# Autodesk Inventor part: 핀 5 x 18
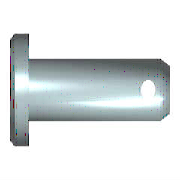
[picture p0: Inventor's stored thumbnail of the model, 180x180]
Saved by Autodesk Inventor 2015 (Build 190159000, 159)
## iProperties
Created: 2012-02
Part Number: 핀 5 x 18
Material: 강철
Description: 머리가 있는 클레비스 핀
Document SubType Name: Modeling
Standard: ISO 2341
Designer: test
Standard Revision: Second edition 1986-11-01
Standards Organization: ISO
Language: ko-KR
Size Designation: B - 5 x 18
Categories: <MemberInstance><Categories><Category DisplayName="조임쇠" InternalName="e4da775c-781d-43d5-af7c-5136215cf5a6" Mnemonic="FSTN"><Category DisplayName="핀" InternalNa
Density: 7.85 g/cm^3
Appearance: 강철
IsCustomPart: 1
Author: test
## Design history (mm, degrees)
sketch "스케치1"
  geometry: L1 (-1.6, 0)-(-1.6, 4); L2 (-1.6, 4)-(0, 4); L3 (0, 4)-(0, 2.5); L4 (0, 2.5)-(18, 2.5); L5 (18, 2.5)-(18, 0); L6 (-1.6, 0)-(18, 0); L7 (-4, 0)-(17, 0) reference; L8 (0, -0.98)-(0, 3.08) reference; C1 r 0.6 at (15.1, 0)
  constraints: 12 end point, 3 parallel, 2 collinear, 2 perpendicular, 1 centre point, 1 point on line, 1 vertical
  dimensions: "d0" = 5 diameter of L4 L6 (= NND); "d1" = 8 diameter of L2 L6 (= KOD); "d2" = 1.6 distance of L1.end L2.end (= KOH); "d3" = 18 distance of L3.end L4.end (= NLG); "d5" = 2.9 distance from line of L5 C1.centre (= DIST); "d6" = 1.2 diameter of C1 (= BOR)
revolve "본체" stored, may be unused: angle "d4" = 90 deg
extrude "구멍" cut sketch "스케치1" stored distance "d7" = 5 (= NND); taper "d8" = 0 deg
workaxis "Work Axis1"
workplane "Work Plane1"
node "작업 평면4"
body "Solid1"
chamfer "모따기1" distance "d9" = 1 (= PHH2); stored, may be unused: angle "d10" = 45 deg (= FAWI2), second distance "d16" = 1 (= PHH2)
chamfer "모따기2" distance "d11" = 2 (= PHH1); stored, may be unused: angle "d12" = 30 deg (= FAWI1), second distance "d17" = 2 (= PHH1)
other parameters: "PHH1" = 2 [user parameter; used in 2 equation terms], "PHH2" = 1 [user parameter; used in 2 equation terms], "KOD" = 8 [user parameter; used in 1 equation term], "KOH" = 1.6 [user parameter; used in 1 equation term], "NND" = 5 [user parameter; used in 2 equation terms], "FAWI1" = 30 deg [user parameter; used in 1 equation term], "FAWI2" = 45 deg [user parameter; used in 1 equation term], "DIST" = 2.9 [user parameter; used in 1 equation term], "BOR" = 1.2 [user parameter; used in 1 equation term], "NLG" = 18 [user parameter; used in 1 equation term], "d13" = 0, "d14" = 0, "d27" = 0, "d28" = 0, "d29" = 0, "d30" = 0, "d31" = 0
